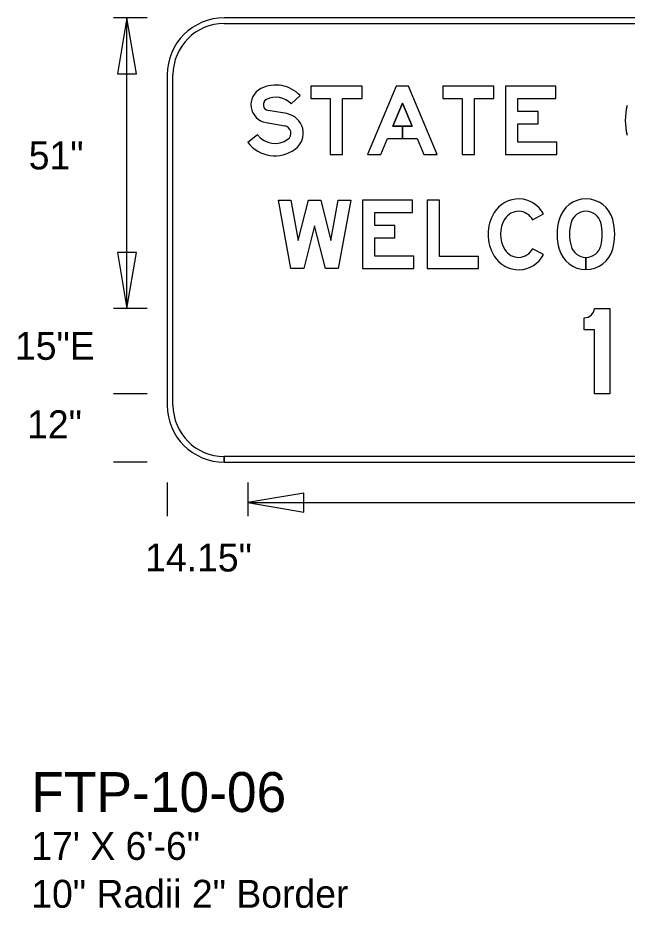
# Model space of a CAD drawing. Extents: x 0 to 770, y 0 to 495.
# Drawn here: x 582.1 to 658.5, y 9 to 120.6 of the extents above; entities that cross this region are included whole.
import ezdxf

# ---------------------------------------------------------------- set-up
doc = ezdxf.new("R2010")
doc.units = 0
for name, color, linetype in [('Dimension', 7, 'Continuous'), ('GSBWFill', 7, 'Continuous'), ('GSColorFill', 7, 'Continuous'), ('GSDims', 7, 'Continuous'), ('GSOutline', 7, 'Continuous'), ('TextStructures', 7, 'Continuous')]:
    doc.layers.add(name, color=color, linetype=linetype)

msp = doc.modelspace()

# ---------------------------------------------------------------- linework, layer by layer
at = {"layer": 'Dimension'}
for points in [[(595.81, 120.6), (594.62, 113.59), (597, 113.59)], [(595.81, 84.2), (597, 91.21), (594.62, 91.21)], [(610.98, 59.86), (617.99, 58.67), (617.99, 61.05)]]:
    msp.add_lwpolyline(points, close=True, dxfattribs=at)
at = {"layer": 'GSBWFill'}
for p, q in [((739.36, 120.6), (608.01, 120.6)), ((739.36, 120.6), (608.01, 120.6)), ((608.01, 119.89), (739.36, 119.89)), ((600.87, 113.46), (600.87, 72.06)), ((600.87, 113.46), (600.87, 72.06)), ((601.58, 72.06), (601.58, 113.46)), ((616.4, 109.81), (617.53, 110.86)), ((615.84, 108.6), (613.51, 108.99)), ((613.25, 107.47), (615.59, 107.08)), ((612.2, 105.93), (610.98, 104.99)), ((646.66, 95.3), (648.03, 96.03)), ((648.03, 90.93), (646.66, 91.65)), ((646.66, 91.65), (646.66, 91.65)), ((653.34, 89.04), (653.34, 90.59)), ((653.34, 90.59), (653.34, 89.04)), ((608.01, 64.92), (608.01, 65.64)), ((739.36, 65.64), (608.01, 65.64)), ((608.01, 65.64), (608.01, 64.92)), ((608.01, 64.92), (739.36, 64.92)), ((608.01, 64.92), (739.36, 64.92))]:
    msp.add_line(p, q, dxfattribs=at)
for points in [[(618.86, 110.5), (621.3, 110.5), (621.3, 103.47), (622.84, 103.47), (622.84, 110.5), (625.28, 110.5), (625.28, 112.04), (618.86, 112.04)], [(631.54, 107.03), (630.34, 107.03), (630.34, 105.48), (632.19, 105.48), (633.03, 103.47), (634.7, 103.47), (631.11, 112.04), (629.56, 112.04), (625.97, 103.47), (627.64, 103.47), (628.48, 105.48), (630.34, 105.48), (630.34, 107.03), (629.13, 107.03), (630.34, 109.89)], [(635.39, 110.5), (637.83, 110.5), (637.83, 103.47), (639.37, 103.47), (639.37, 110.5), (641.81, 110.5), (641.81, 112.04), (635.39, 112.04)], [(649.7, 105.01), (644.81, 105.01), (644.81, 107.32), (647.34, 107.32), (647.34, 108.86), (644.81, 108.86), (644.81, 110.5), (649.57, 110.5), (649.57, 112.04), (643.27, 112.04), (643.27, 103.47), (649.7, 103.47)], [(619.33, 94.55), (617.98, 89.19), (616.35, 89.19), (614.79, 97.76), (616.36, 97.76), (617.28, 92.71), (618.55, 97.76), (620.11, 97.76), (621.38, 92.71), (622.3, 97.76), (623.87, 97.76), (622.3, 89.19), (620.68, 89.19)], [(631.75, 90.74), (626.87, 90.74), (626.87, 93.04), (629.39, 93.04), (629.39, 94.58), (626.87, 94.58), (626.87, 96.22), (631.62, 96.22), (631.62, 97.76), (625.32, 97.76), (625.32, 89.19), (631.75, 89.19)], [(639.89, 89.19), (639.89, 90.69), (635, 90.69), (635, 97.76), (633.46, 97.76), (633.46, 89.19)]]:
    msp.add_lwpolyline(points, close=True, dxfattribs=at)
for points in [[(654.41, 84.2), (656.33, 84.2), (656.33, 73.49)], [(656.33, 73.49), (654.41, 73.49), (654.41, 81.52), (653.12, 81.52), (653.12, 83.02)]]:
    msp.add_lwpolyline(points, dxfattribs=at)
for centre, radius, start, end in [((608.01, 113.46), 7.14, 90, 180), ((608.01, 113.46), 7.14, 90, 180), ((608.01, 113.46), 6.42, 90, 180), ((613.63, 109.71), 2.27, 116.9123, 260.4087), ((614.48, 108.03), 4.15, 42.8759, 116.9123), ((614.48, 108.03), 2.61, 42.8759, 116.9123), ((613.63, 109.71), 0.728, 116.9123, 260.4087), ((665.46, 107.75), 7.2, 165.0382, 194.9618), ((615.43, 106.15), 2.48, 306.123, 80.4087), ((615.43, 106.15), 0.942, 306.123, 80.4087), ((614.37, 107.6), 4.28, 217.5895, 306.123), ((614.37, 107.6), 2.74, 217.5895, 306.123), ((653.34, 94.44), 3.47, 14.9618, 165.0382), ((653.34, 94.44), 1.93, 14.9618, 165.0382), ((656.93, 93.48), 7.2, 165.0382, 194.9618), ((656.93, 93.48), 5.65, 165.0382, 194.9618), ((649.74, 93.48), 5.65, 345.0382, 14.9618), ((649.74, 93.48), 7.2, 345.0382, 14.9618), ((653.34, 92.52), 3.47, 194.9618, 270), ((653.34, 92.52), 1.93, 194.9618, 270), ((653.34, 92.52), 1.93, 270.0127, 345.0382), ((653.34, 92.52), 3.47, 270.0071, 345.0382), ((653.12, 84.31), 1.29, 270, 355.0209), ((608.01, 72.06), 7.14, 180, 270), ((608.01, 72.06), 7.14, 180, 270), ((608.01, 72.06), 6.42, 180, 270)]:
    msp.add_arc(centre, radius, start, end, dxfattribs=at)
for centre, major_axis, start_param, end_param in [((644.89, 94.35), (0, 3.56), 5.201543, 7.308565), ((646.33, 93.48), (0, 5.25), 1.025379, 2.116213), ((644.89, 94.35), (0, 2.01), 5.201543, 7.308565), ((646.33, 93.48), (0, 3.71), 1.025379, 2.116213), ((644.89, 92.6), (0, 2.01), 2.116213, 4.223235), ((644.89, 92.6), (0, 3.56), 2.116213, 4.223235)]:
    msp.add_ellipse(centre, major_axis=major_axis, ratio=0.999994, start_param=start_param, end_param=end_param, dxfattribs=at)
at = {"layer": 'GSColorFill'}
for p, q in [((616.4, 109.81), (617.53, 110.86)), ((615.84, 108.6), (613.51, 108.99)), ((613.25, 107.47), (615.59, 107.08)), ((612.2, 105.93), (610.98, 104.99)), ((646.66, 95.3), (648.03, 96.03)), ((648.03, 90.93), (646.66, 91.65)), ((646.66, 91.65), (646.66, 91.65)), ((653.34, 89.04), (653.34, 90.59)), ((653.34, 90.59), (653.34, 89.04))]:
    msp.add_line(p, q, dxfattribs=at)
for points in [[(618.86, 110.5), (621.3, 110.5), (621.3, 103.47), (622.84, 103.47), (622.84, 110.5), (625.28, 110.5), (625.28, 112.04), (618.86, 112.04)], [(631.54, 107.03), (630.34, 107.03), (630.34, 105.48), (632.19, 105.48), (633.03, 103.47), (634.7, 103.47), (631.11, 112.04), (629.56, 112.04), (625.97, 103.47), (627.64, 103.47), (628.48, 105.48), (630.34, 105.48), (630.34, 107.03), (629.13, 107.03), (630.34, 109.89)], [(635.39, 110.5), (637.83, 110.5), (637.83, 103.47), (639.37, 103.47), (639.37, 110.5), (641.81, 110.5), (641.81, 112.04), (635.39, 112.04)], [(649.7, 105.01), (644.81, 105.01), (644.81, 107.32), (647.34, 107.32), (647.34, 108.86), (644.81, 108.86), (644.81, 110.5), (649.57, 110.5), (649.57, 112.04), (643.27, 112.04), (643.27, 103.47), (649.7, 103.47)], [(619.33, 94.55), (617.98, 89.19), (616.35, 89.19), (614.79, 97.76), (616.36, 97.76), (617.28, 92.71), (618.55, 97.76), (620.11, 97.76), (621.38, 92.71), (622.3, 97.76), (623.87, 97.76), (622.3, 89.19), (620.68, 89.19)], [(631.75, 90.74), (626.87, 90.74), (626.87, 93.04), (629.39, 93.04), (629.39, 94.58), (626.87, 94.58), (626.87, 96.22), (631.62, 96.22), (631.62, 97.76), (625.32, 97.76), (625.32, 89.19), (631.75, 89.19)], [(639.89, 89.19), (639.89, 90.69), (635, 90.69), (635, 97.76), (633.46, 97.76), (633.46, 89.19)]]:
    msp.add_lwpolyline(points, close=True, dxfattribs=at)
for points in [[(654.41, 84.2), (656.33, 84.2), (656.33, 73.49)], [(656.33, 73.49), (654.41, 73.49), (654.41, 81.52), (653.12, 81.52), (653.12, 83.02)]]:
    msp.add_lwpolyline(points, dxfattribs=at)
for centre, radius, start, end in [((613.63, 109.71), 2.27, 116.9123, 260.4087), ((614.48, 108.03), 4.15, 42.8759, 116.9123), ((614.48, 108.03), 2.61, 42.8759, 116.9123), ((613.63, 109.71), 0.728, 116.9123, 260.4087), ((665.46, 107.75), 7.2, 165.0382, 194.9618), ((615.43, 106.15), 2.48, 306.123, 80.4087), ((615.43, 106.15), 0.942, 306.123, 80.4087), ((614.37, 107.6), 4.28, 217.5895, 306.123), ((614.37, 107.6), 2.74, 217.5895, 306.123), ((653.34, 94.44), 3.47, 14.9618, 165.0382), ((653.34, 94.44), 1.93, 14.9618, 165.0382), ((656.93, 93.48), 7.2, 165.0382, 194.9618), ((656.93, 93.48), 5.65, 165.0382, 194.9618), ((649.74, 93.48), 5.65, 345.0382, 14.9618), ((649.74, 93.48), 7.2, 345.0382, 14.9618), ((653.34, 92.52), 3.47, 194.9618, 270), ((653.34, 92.52), 1.93, 194.9618, 270), ((653.34, 92.52), 1.93, 270.0127, 345.0382), ((653.34, 92.52), 3.47, 270.0071, 345.0382), ((653.12, 84.31), 1.29, 270, 355.0209)]:
    msp.add_arc(centre, radius, start, end, dxfattribs=at)
for centre, major_axis, start_param, end_param in [((644.89, 94.35), (0, 3.56), 5.201543, 7.308565), ((646.33, 93.48), (0, 5.25), 1.025379, 2.116213), ((644.89, 94.35), (0, 2.01), 5.201543, 7.308565), ((646.33, 93.48), (0, 3.71), 1.025379, 2.116213), ((644.89, 92.6), (0, 2.01), 2.116213, 4.223235), ((644.89, 92.6), (0, 3.56), 2.116213, 4.223235)]:
    msp.add_ellipse(centre, major_axis=major_axis, ratio=0.999994, start_param=start_param, end_param=end_param, dxfattribs=at)
at = {"layer": 'GSDims'}
for p, q in [((598.34, 120.6), (594.12, 120.6)), ((595.81, 84.2), (595.81, 120.6)), ((598.34, 84.2), (594.12, 84.2)), ((598.34, 84.2), (594.12, 84.2)), ((598.34, 73.49), (594.12, 73.49)), ((598.34, 73.49), (594.12, 73.49)), ((598.34, 64.92), (594.12, 64.92)), ((600.87, 62.39), (600.87, 58.18)), ((610.98, 62.39), (610.98, 58.18)), ((610.98, 62.39), (610.98, 58.18)), ((610.98, 59.86), (736.39, 59.86))]:
    msp.add_line(p, q, dxfattribs=at)
at = {"layer": 'GSOutline'}
for p, q in [((616.4, 109.81), (617.53, 110.86)), ((615.84, 108.6), (613.51, 108.99)), ((613.25, 107.47), (615.59, 107.08)), ((612.2, 105.93), (610.98, 104.99)), ((646.66, 95.3), (648.03, 96.03)), ((648.03, 90.93), (646.66, 91.65)), ((646.66, 91.65), (646.66, 91.65))]:
    msp.add_line(p, q, dxfattribs=at)
for points in [[(618.86, 110.5), (621.3, 110.5), (621.3, 103.47), (622.84, 103.47), (622.84, 110.5), (625.28, 110.5), (625.28, 112.04), (618.86, 112.04)], [(628.48, 105.48), (632.19, 105.48), (633.03, 103.47), (634.7, 103.47), (631.11, 112.04), (629.56, 112.04), (625.97, 103.47), (627.64, 103.47)], [(635.39, 110.5), (637.83, 110.5), (637.83, 103.47), (639.37, 103.47), (639.37, 110.5), (641.81, 110.5), (641.81, 112.04), (635.39, 112.04)], [(649.7, 105.01), (644.81, 105.01), (644.81, 107.32), (647.34, 107.32), (647.34, 108.86), (644.81, 108.86), (644.81, 110.5), (649.57, 110.5), (649.57, 112.04), (643.27, 112.04), (643.27, 103.47), (649.7, 103.47)], [(631.54, 107.03), (630.34, 109.89), (629.13, 107.03)], [(619.33, 94.55), (617.98, 89.19), (616.35, 89.19), (614.79, 97.76), (616.36, 97.76), (617.28, 92.71), (618.55, 97.76), (620.11, 97.76), (621.38, 92.71), (622.3, 97.76), (623.87, 97.76), (622.3, 89.19), (620.68, 89.19)], [(631.75, 90.74), (626.87, 90.74), (626.87, 93.04), (629.39, 93.04), (629.39, 94.58), (626.87, 94.58), (626.87, 96.22), (631.62, 96.22), (631.62, 97.76), (625.32, 97.76), (625.32, 89.19), (631.75, 89.19)], [(639.89, 89.19), (639.89, 90.69), (635, 90.69), (635, 97.76), (633.46, 97.76), (633.46, 89.19)]]:
    msp.add_lwpolyline(points, close=True, dxfattribs=at)
for points in [[(654.41, 84.2), (656.33, 84.2), (656.33, 73.49)], [(656.33, 73.49), (654.41, 73.49), (654.41, 81.52), (653.12, 81.52), (653.12, 83.02)]]:
    msp.add_lwpolyline(points, dxfattribs=at)
for centre, radius, start, end in [((613.63, 109.71), 2.27, 116.9123, 260.4087), ((614.48, 108.03), 4.15, 42.8759, 116.9123), ((614.48, 108.03), 2.61, 42.8759, 116.9123), ((613.63, 109.71), 0.728, 116.9123, 260.4087), ((665.46, 107.75), 7.2, 165.0382, 194.9618), ((615.43, 106.15), 2.48, 306.123, 80.4087), ((615.43, 106.15), 0.942, 306.123, 80.4087), ((614.37, 107.6), 4.28, 217.5895, 306.123), ((614.37, 107.6), 2.74, 217.5895, 306.123), ((653.34, 94.44), 3.47, 14.9618, 165.0382), ((653.34, 94.44), 1.93, 14.9618, 165.0382), ((656.93, 93.48), 7.2, 165.0382, 194.9618), ((656.93, 93.48), 5.65, 165.0382, 194.9618), ((649.74, 93.48), 5.65, 345.0382, 14.9618), ((649.74, 93.48), 7.2, 345.0382, 14.9618), ((653.34, 92.52), 3.47, 194.9618, 345.0382), ((653.34, 92.52), 1.93, 194.9618, 345.0382), ((653.12, 84.31), 1.29, 270, 355.0209)]:
    msp.add_arc(centre, radius, start, end, dxfattribs=at)
for centre, major_axis, start_param, end_param in [((644.89, 94.35), (0, 3.56), 5.201543, 7.308565), ((646.33, 93.48), (0, 5.25), 1.025379, 2.116213), ((644.89, 94.35), (0, 2.01), 5.201543, 7.308565), ((646.33, 93.48), (0, 3.71), 1.025379, 2.116213), ((644.89, 92.6), (0, 2.01), 2.116213, 4.223235), ((644.89, 92.6), (0, 3.56), 2.116213, 4.223235)]:
    msp.add_ellipse(centre, major_axis=major_axis, ratio=0.999994, start_param=start_param, end_param=end_param, dxfattribs=at)

# ---------------------------------------------------------------- texts
at = {"layer": 'TextStructures'}
for s, height, p in [('51"', 3.5, (583.51, 101.61)), ('15"E', 3.5, (581.79, 77.75)), ('12"', 3.5, (583.31, 67.92)), ('14.15"', 3.5, (598.1, 51.23)), ('FTP-10-06', 5, (583.83, 21.09)), ('17\' X 6\'-6"', 3.5, (583.83, 15.09)), ('10" Radii 2" Border', 3.5, (583.83, 9.09))]:
    msp.add_text(s, height=height, dxfattribs=at).set_placement(p)

doc.saveas('drawing.dxf')
